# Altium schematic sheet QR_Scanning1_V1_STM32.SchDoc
size 381 x 241 mm; SheetNumber: 2; SheetTotal: 3
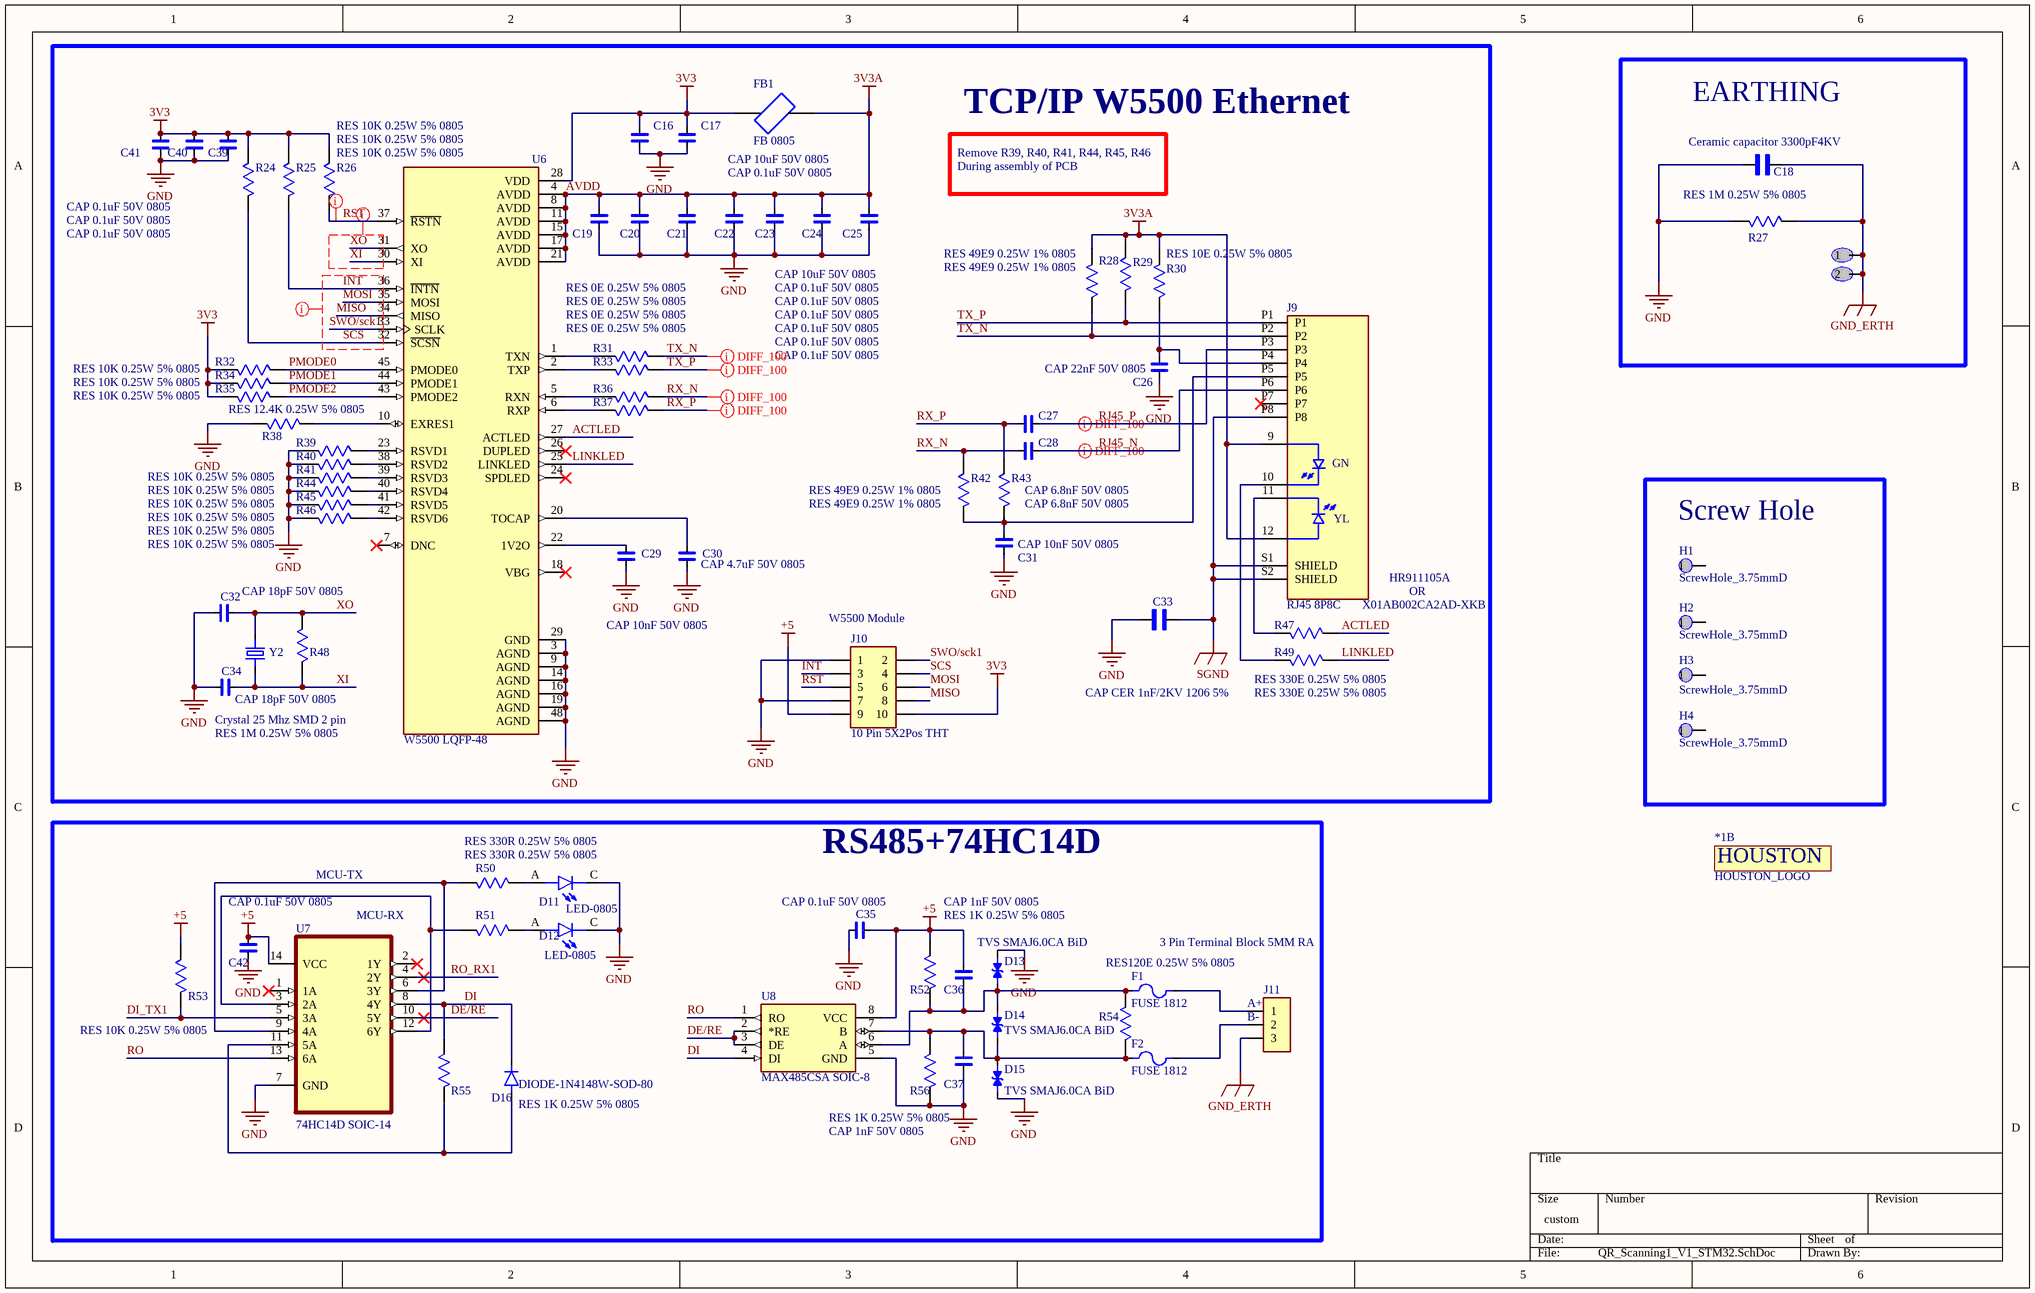
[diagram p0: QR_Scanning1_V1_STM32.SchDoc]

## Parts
*1  HOUSTON_LOGO  [HOUSTON_LOGO]  (part B of 2)
C16  CAP 0.1uF 50V 0805  [CAP CER 0.1uF/50V 5%]
C17  CAP 10uF 50V 0805  [CAP CER 0.1uF/50V 5%]
C18  Ceramic capacitor 3300pF4KV  [Ceramic capacitor 3300pF4KV]
C19  CAP 0.1uF 50V 0805  [CAP CER 0.1uF/50V 5%]
C20  CAP 0.1uF 50V 0805  [CAP CER 0.1uF/50V 5%]
C21  CAP 0.1uF 50V 0805  [CAP CER 0.1uF/50V 5%]
C22  CAP 0.1uF 50V 0805  [CAP CER 0.1uF/50V 5%]
C23  CAP 0.1uF 50V 0805  [CAP CER 0.1uF/50V 5%]
C24  CAP 0.1uF 50V 0805  [CAP CER 0.1uF/50V 5%]
C25  CAP 10uF 50V 0805  [CAP CER 0.1uF/50V 5%]
C26  CAP 22nF 50V 0805  [CAP CER 0.1uF/50V 5%]
C27  CAP 6.8nF 50V 0805  [CAP CER 0.1uF/50V 5%]
C28  CAP 6.8nF 50V 0805  [CAP CER 0.1uF/50V 5%]
C29  CAP 10nF 50V 0805  [CAP CER 0.1uF/50V 5%]
C30  CAP 4.7uF 50V 0805  [CAP CER 0.1uF/50V 5%]
C31  CAP 10nF 50V 0805  [CAP CER 0.1uF/50V 5%]
C32  CAP 18pF 50V 0805  [CAP CER 0.1uF/50V 5%]
C33  CAP CER 1nF/2KV 1206 5%  [CAP CER 1nF/2KV 1206 5%]
C34  CAP 18pF 50V 0805  [CAP CER 0.1uF/50V 5%]
C35  CAP 0.1uF 50V 0805  [CAP CER 0.1uF/50V 5%]
C36  CAP 1nF 50V 0805  [CAP CER 0.1uF/50V 5%]
C37  CAP 1nF 50V 0805  [CAP CER 0.1uF/50V 5%]
C39  CAP 0.1uF 50V 0805  [CAP CER 0.1uF/50V 5%]
C40  CAP 0.1uF 50V 0805  [CAP CER 0.1uF/50V 5%]
C41  CAP 0.1uF 50V 0805  [CAP CER 0.1uF/50V 5%]
C42  CAP 0.1uF 50V 0805  [CAP CER 0.1uF/50V 5%]
D11  LED-0805  [LED-0805]
D12  LED-0805  [LED-0805]
D13  TVS SMAJ6.0CA BiD  [TVS SMAJ6.0CA DO-214AC (SMA)]
D14  TVS SMAJ6.0CA BiD  [TVS SMAJ6.0CA DO-214AC (SMA)]
D15  TVS SMAJ6.0CA BiD  [TVS SMAJ6.0CA DO-214AC (SMA)]
D16  DIODE-1N4148W-SOD-80  [DIODE-1N4148W-SOD-80]
EARTHING_VIA_HOLE_3.65MM  EARTHING_VIA HOLE_3.65MM  [EARTHING_VIA HOLE_3.65MM]  (value not drawn)
F1  FUSE 1812  [FUSE 1812]
F2  FUSE 1812  [FUSE 1812]
FB1  FB 0805  [FB 0805]
H1  ScrewHole_3.75mmD  [ScrewHole_3.75mmD - duplicate]
H2  ScrewHole_3.75mmD  [ScrewHole_3.75mmD - duplicate]
H3  ScrewHole_3.75mmD  [ScrewHole_3.75mmD - duplicate]
H4  ScrewHole_3.75mmD  [ScrewHole_3.75mmD - duplicate]
J9  RJ45 8P8C  [RJ45 8P8C]
J10  10 Pin 5X2Pos THT  [10 Pin 5X2Pos THT]
J11  3 Pin Terminal Block 5MM RA  [3 Pin Terminal Block 5MM RA]
R24  RES 10K 0.25W 5% 0805  [RES 0805 10K/0.25W 5%]
R25  RES 10K 0.25W 5% 0805  [RES 0805 10K/0.25W 5%]
R26  RES 10K 0.25W 5% 0805  [RES 0805 10K/0.25W 5%]
R27  RES 1M 0.25W 5% 0805  [RES 0805 10K/0.25W 5%]
R28  RES 49E9 0.25W 1% 0805  [RES 0805 10K/0.25W 5%]
R29  RES 49E9 0.25W 1% 0805  [RES 0805 10K/0.25W 5%]
R30  RES 10E 0.25W 5% 0805  [RES 0805 10K/0.25W 5%]
R31  RES 0E 0.25W 5% 0805  [RES 0805 10K/0.25W 5%]
R32  RES 10K 0.25W 5% 0805  [RES 0805 10K/0.25W 5%]
R33  RES 0E 0.25W 5% 0805  [RES 0805 10K/0.25W 5%]
R34  RES 10K 0.25W 5% 0805  [RES 0805 10K/0.25W 5%]
R35  RES 10K 0.25W 5% 0805  [RES 0805 10K/0.25W 5%]
R36  RES 0E 0.25W 5% 0805  [RES 0805 10K/0.25W 5%]
R37  RES 0E 0.25W 5% 0805  [RES 0805 10K/0.25W 5%]
R38  RES 12.4K 0.25W 5% 0805  [RES 0805 10K/0.25W 5%]
R39  RES 10K 0.25W 5% 0805  [RES 0805 10K/0.25W 5%]
R40  RES 10K 0.25W 5% 0805  [RES 0805 10K/0.25W 5%]
R41  RES 10K 0.25W 5% 0805  [RES 0805 10K/0.25W 5%]
R42  RES 49E9 0.25W 1% 0805  [RES 0805 10K/0.25W 5%]
R43  RES 49E9 0.25W 1% 0805  [RES 0805 10K/0.25W 5%]
R44  RES 10K 0.25W 5% 0805  [RES 0805 10K/0.25W 5%]
R45  RES 10K 0.25W 5% 0805  [RES 0805 10K/0.25W 5%]
R46  RES 10K 0.25W 5% 0805  [RES 0805 10K/0.25W 5%]
R47  RES 330E 0.25W 5% 0805  [RES 0805 10K/0.25W 5%]
R48  RES 1M 0.25W 5% 0805  [RES 0805 10K/0.25W 5%]
R49  RES 330E 0.25W 5% 0805  [RES 0805 10K/0.25W 5%]
R50  RES 330R 0.25W 5% 0805  [RES 0805 10K/0.25W 5%]
R51  RES 330R 0.25W 5% 0805  [RES 0805 10K/0.25W 5%]
R52  RES 1K 0.25W 5% 0805  [RES 0805 10K/0.25W 5%]
R53  RES 10K 0.25W 5% 0805  [RES 0805 10K/0.25W 5%]
R54  RES120E 0.25W 5% 0805  [RES 0805 10K/0.25W 5%]
R55  RES 1K 0.25W 5% 0805  [RES 0805 10K/0.25W 5%]
R56  RES 1K 0.25W 5% 0805  [RES 0805 10K/0.25W 5%]
U6  W5500 LQFP-48  [W5500 LQFP-48]
U7  74HC14D SOIC-14  [74HC14D SOIC-14]
U8  MAX485CSA SOIC-8  [MAX485CSA]
Y2  Crystal 25 Mhz SMD 2 pin  [Crystal 16 Mhz SMD 2 pin]

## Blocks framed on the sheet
TCP/IP W5500 Ethernet: C16 C17 C19-C34 C39-C41 FB1 J9 J10 R24-R26 R28-R49 U6 Y2
EARTHING: C18 EARTHING_VIA_HOLE_3.65MM R27
Screw Hole: H1-H4
RS485+74HC14D: C35-C37 C42 D11-D16 F1 F2 J11 R50-R56 U7 U8

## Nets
3V3: C16.2 C17.2 C39.2 C40.2 C41.2 FB1.1 J10.10 R24.2 R25.2 R26.2 R32.2 R34.2 R35.2 U6.28(VDD)
+5: C35.1 C36.2 C42.2 J10.9 R52.1 R53.2 U7.14(VCC) U8.8(VCC)
AVDD: C19.2 C20.2 C21.2 C22.2 C23.2 C24.2 C25.2 FB1.2 J9.9 J9.12 R28.2 R29.2 R30.2 U6.4(AVDD) U6.8(AVDD) U6.11(AVDD) U6.15(AVDD) U6.17(AVDD) U6.21(AVDD)  [also labelled 3V3A]
GND: C16.1 C17.1 C18.1 C19.1 C20.1 C21.1 C22.1 C23.1 C24.1 C25.1 C26.1 C29.1 C30.1 C31.1 C32.2 C33.1 C34.2 C35.2 C37.2 C39.1 C40.1 C41.1 C42.1 D11.C D12.C D13.2 D15.1 J10.1 J10.7 R27.1 R38.1 R39.2 R40.2 R41.2 R44.2 R45.2 R46.2 R56.1 U6.3(AGND) U6.9(AGND) U6.14(AGND) U6.16(AGND) U6.19(AGND) U6.29(GND) U6.48(AGND) U7.7(GND) U8.5(GND)
GND_ERTH: C18.2 EARTHING_VIA_HOLE_3.65MM.1 EARTHING_VIA_HOLE_3.65MM.2 J11.3 R27.2
SGND: C33.2 J9.P8 J9.S1(SHIELD) J9.S2(SHIELD)
ACTLED: R47.1 U6.27(ACTLED)
DE/RE: U7.10(5Y) U8.2(*RE) U8.3(DE)
DI: D16.C(K) R55.2 U7.8(4Y) U8.4(DI)
DI_TX1: R53.1 U7.5(3A)
INT: J10.3 R25.1 U6.36(~{INTN})
LINKLED: R49.1 U6.25(LINKLED)
MISO: J10.8 U6.34(MISO)
MOSI: J10.6 U6.35(MOSI)
PMODE0: R32.1 U6.45(PMODE0)
PMODE1: R34.1 U6.44(PMODE1)
PMODE2: R35.1 U6.43(PMODE2)
RJ45_N: C28.1 J9.P6
RJ45_P: C27.1 J9.P3
RO: U7.13(6A) U8.1(RO)
RO_RX1: U7.4(2Y)
RST: J10.5 R26.1 U6.37(~{RSTN})
RX_N: C28.2 R36.1 R42.2
RX_P: C27.2 R37.1 R43.2
SCS: J10.4 R24.1 U6.32(~{SCSN})
SWO/sck1: J10.2 U6.33(SCLK)
TX_N: J9.P2 R28.1 R31.1
TX_P: J9.P1 R29.1 R33.1
XI: C34.1 R48.1 U6.30(XI) Y2.2
XO: C32.1 R48.2 U6.31(XO) Y2.1
NetC26_2: C26.2 J9.P4 R30.1
NetC29_2: C29.2 U6.22(1V2O)
NetC30_2: C30.2 U6.20(TOCAP)
NetC31_2: C31.2 J9.P5 R42.1 R43.1
NetC36_1: C36.1 D13.1 D14.2 F1.1 R52.2 R54.2 U8.6(A)
NetC37_1: C37.1 D14.1 D15.2 F2.1 R54.1 R56.2 U8.7(B)
NetD11_A: D11.A R50.1
NetD12_A: D12.A R51.1
NetD16_A: D16.A R55.1 U7.11(5A)
NetF1_2: F1.2 J11.1
NetF2_2: F2.2 J11.2
NetJ9_10: J9.10 R49.2
NetJ9_11: J9.11 R47.2
NetR31_2: R31.2 U6.1(TXN)
NetR33_2: R33.2 U6.2(TXP)
NetR36_2: R36.2 U6.5(RXN)
NetR37_2: R37.2 U6.6(RXP)
NetR38_2: R38.2 U6.10(EXRES1)
NetR39_1: R39.1 U6.23(RSVD1)
NetR40_1: R40.1 U6.38(RSVD2)
NetR41_1: R41.1 U6.39(RSVD3)
NetR44_1: R44.1 U6.40(RSVD4)
NetR45_1: R45.1 U6.41(RSVD5)
NetR46_1: R46.1 U6.42(RSVD6)
NetR50_2: R50.2 U7.6(3Y) U7.9(4A)
NetR51_2: R51.2 U7.3(2A) U7.12(6Y)

Not connected (* = marked no-connect by the designer): H1 1; H2 1; H3 1; H4 1; J9 P7*; U6 7(DNC)* 18(VBG)* 24(SPDLED)* 26(DUPLED)*; U7 1(1A)* 2(1Y)*

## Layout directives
net class Single_50 ohm: INT, MISO, MOSI, RST, SCS, SWO/sck1, XI, XO
differential pair; differential pair class DIFF_100: RJ45_N, RJ45_P, RX_N, RX_P, TX_N, TX_P

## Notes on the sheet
- Remove R39, R40, R41, R44, R45, R46
- During assembly of PCB
- (near J10) W5500 Module
- X01AB002CA2AD-XKB
- HR911105A
- OR
- MCU-TX
- (near U7) MCU-RX
- (near J11) B-
- (near J11) A+

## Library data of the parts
C16 C17 C19-C32 C34-C37 C39-C42 = CAP CER 0.1uF/50V 5%: CAP CER 0.1uF/50V  Ceramic Capacitor X7R 0805 (2012 Metric) SMT; MF: Samsung; MP: CL21B104KCFNNNE
C18 = Ceramic capacitor 3300pF4KV: Ceramic capacitor 3300pF4KV, Tension nominale 400Vac(r.m.s.), 4KV ESD, DE2E3SA332MA3BY02F; MF: Murata
C33 = CAP CER 1nF/2KV 1206 5%: 1000 pF Â±10% 2000V (2kV) Ceramic Capacitor X7R 1206 (3216 Metric) C1206C102KGRACAUTO; MF: KEMET
D11 D12 = LED-0805: Red 640nm LED Indication - Discrete 1.85V 0805 (2012 Metric) APT2012SRCPRV; MF: Kingbright
D13-D15 = TVS SMAJ6.0CA DO-214AC (SMA): SMAJ6.0CA WG Bidirectional TVS diode littlefuse DO-214AC (SMA); MP: SMAJ7.5CA
D16 = DIODE-1N4148W-SOD-80: DIODE-1N4148W-SOD-80 is a general-purpose silicon diode LL4148_L1G
F1 F2 = FUSE 1812: Polymeric PTC Resettable Fuse 60V 100 mA Ih Surface Mount 1812 (4532 Metric), Concave, MF-MSMF010-2; MF: Bourns
FB1 = FB 0805: MH2029-101Y-Bourns Inc.-Ferrite Bead, 100 Ohms @ 100 MHz , Signal Line Ferrite Bead 0805 (2012 Metric) 2A 100mOhm; MP: MPZ2012S102AT000
H1-H4 = ScrewHole_3.75mmD: SCREW HEAD DIA 4.5MM, SREW LEG DIA 3 MM
J9 = RJ45 8P8C: 10/100 BaseT, 8P8C, Horizontal, Shielded, LED, Through Hole, 6 Âµin Plating, RJ45 with Integrated Magnetics Modular Connector CRJ011-ML1-TH; MF: Same Sky
J10 = 10 Pin 5X2Pos THT: 10 Pin 5X2Pos THT BergeStick 2.54MM MTSW-105-X-X-D-X; MF: {'manufacturer': u'Samtec Inc.'}
J11 = 3 Pin Terminal Block 5MM RA: 3 Pin Terminal Block HDR 5MM THT RA 231-433_001-000; MP: 231-433/001-000; MF: WAGO
R24-R26 R28-R56 = RES 10K 0.25W 5% 0805: RESISTOR, THICK FILM, 10K, 5%, 0805 0.25W SMT; MP: ERJ-6GEYJ103V; MF: Panasonic Electronic
R27 = RES 10K 0.25W 5% 0805: RESISTOR, THICK FILM, 1M, 5%, 0805 0.25W SMT; MP: ERJ-6GEYJ103V; MF: Panasonic Electronic
U6 = W5500: W5500 LQFP-48 Hardwired TCP/IP embedded Ethernet controller
U7 = 74HC14D,653: Inverter IC 6 Channel Schmitt Trigger 14-SO/SOIC-14; MF: Nexperia USA
U8 = MAX485CSA: MAX485CSA-RS-485/RS-422 Transceivers, SOIC-8; MF: Analog Devices; MP: MAX485CSA+
Y2 = Crystal 16 Mhz SMD 2 pin_1: 16 MHz Â±30ppm Crystal 20pF 60 Ohms HC-49/US FOXSDLF/128-20 16 Mhz Crystal SMD –CSM-4ALX(28ALX) 12.5mmX4.85mmX4mm; MF: Fox Electronics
